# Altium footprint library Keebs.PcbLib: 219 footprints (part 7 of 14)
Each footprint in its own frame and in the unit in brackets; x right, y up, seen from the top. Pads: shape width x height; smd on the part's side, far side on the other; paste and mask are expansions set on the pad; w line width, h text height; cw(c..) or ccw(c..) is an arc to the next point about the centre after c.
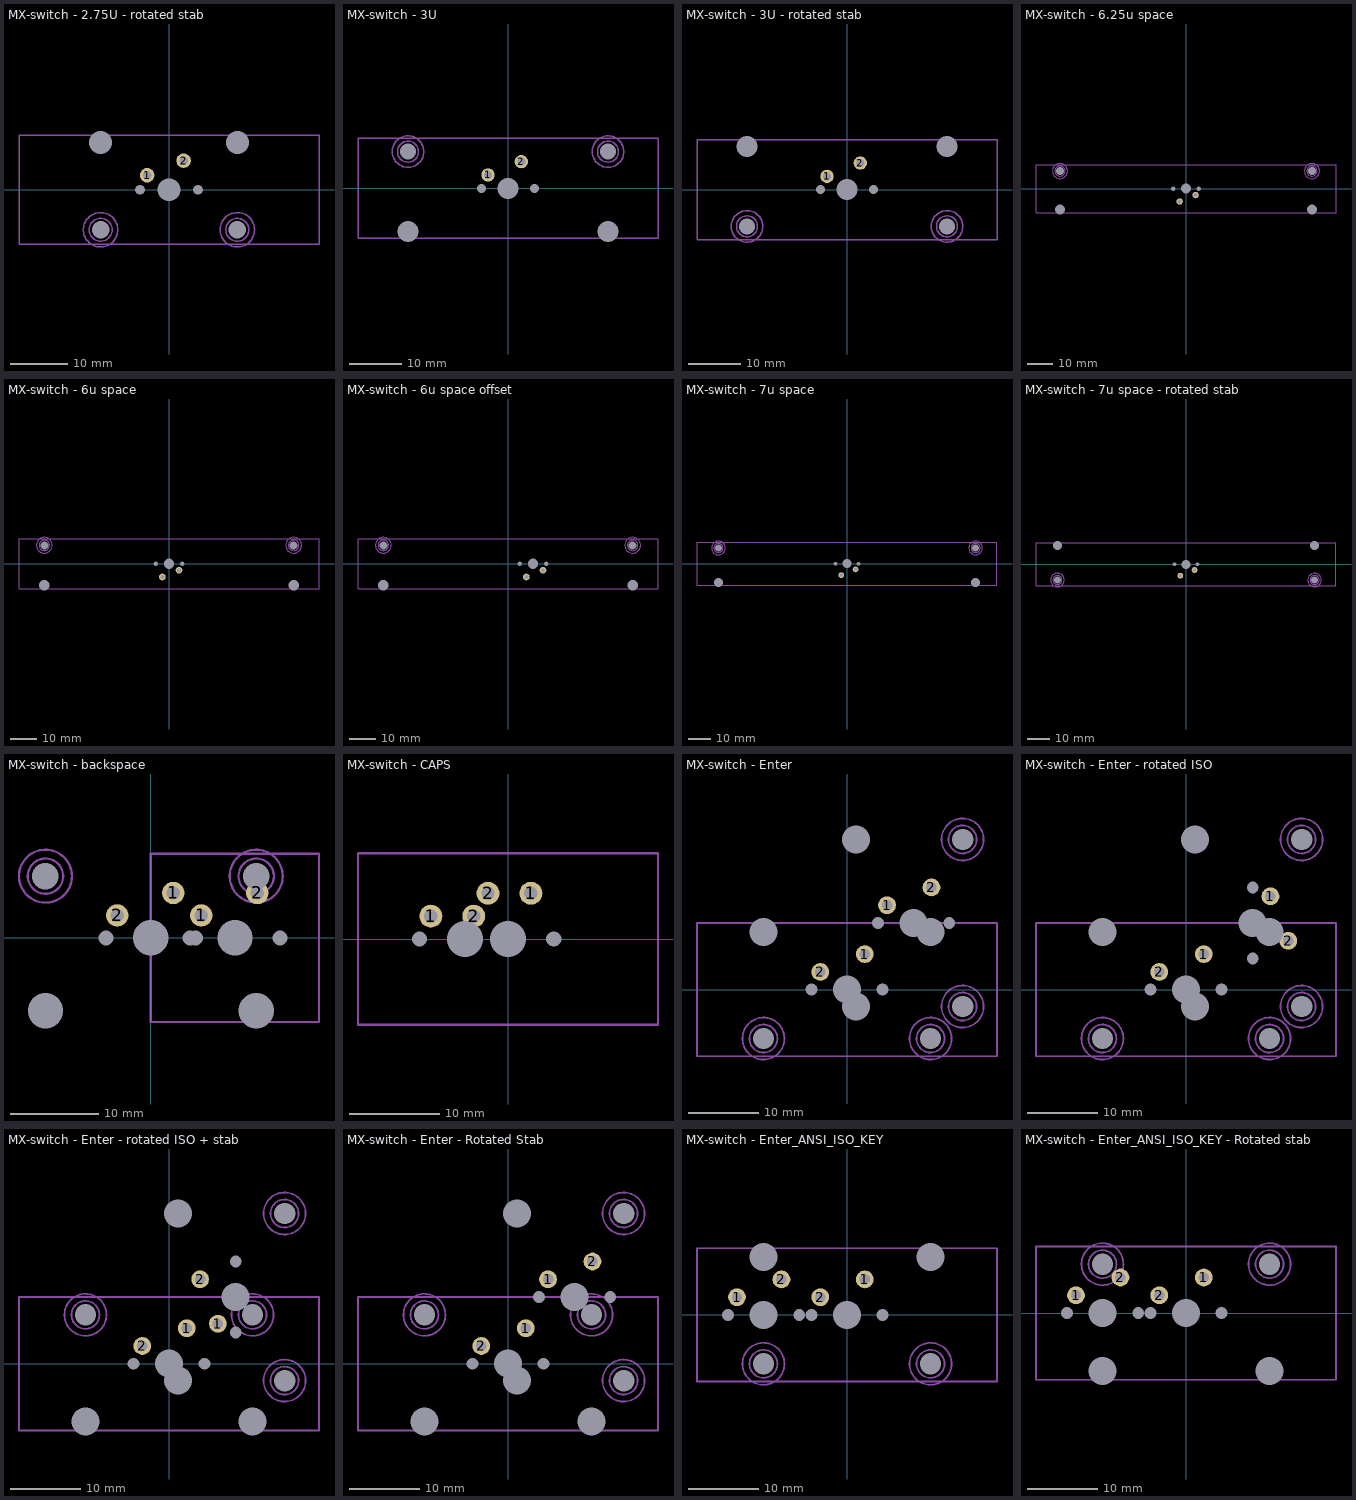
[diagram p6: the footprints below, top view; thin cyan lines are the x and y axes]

## MX-switch - 2.75U - rotated stab [mm]
pads (10):
  round 2.54 hole 1.5 mask-0.5: 1(-3.81,2.54) 2(2.54,5.08)
  round 1.524 hole 3.048 unplated: ""(-11.938,-6.985) ""(11.938,-6.985)
  round 1.524 hole 4 unplated: ""(-11.938,8.255) ""(11.938,8.255)
  round 1 hole 1.7 unplated: ""(-5.08,0) ""(5.08,0)
  round 1 on Mech13: ""(0,0)
  round 1 hole 4 unplated: ""(0,0)
Mechanical 13:
  lines w0.254: -26.194,-9.525 -26.194,9.525 26.194,9.525 26.194,-9.525 -26.194,-9.525
  text ".Designator" at -3.825,-3.375 h0.7
Mechanical 15:
  circle w0.254: c-11.938,-6.985 r2
  circle w0.254: c-11.938,-6.985 r3
  circle w0.254: c11.938,-6.985 r2
  circle w0.254: c11.938,-6.985 r3

## MX-switch - 3U [mm]
pads (10):
  round 2.54 hole 1.5 mask-0.5: 1(-3.81,2.54) 2(2.54,5.08)
  round 1.524 hole 4 unplated: ""(-19.05,-8.255) ""(19.05,-8.255)
  round 1.524 hole 3.048 unplated: ""(-19.05,6.985) ""(19.05,6.985)
  round 1 hole 1.7 unplated: ""(-5.08,0) ""(5.08,0)
  round 1 on Mech13: ""(0,0)
  round 1 hole 4 unplated: ""(0,0)
Mechanical 13:
  lines w0.254: -28.575,-9.525 28.575,-9.525 28.575,9.525 -28.575,9.525 -28.575,-9.525
  text ".Designator" at -3.825,-3.375 h0.7
Mechanical 15:
  circle w0.254: c-19.05,6.985 r3
  circle w0.254: c-19.05,6.985 r2
  circle w0.254: c19.05,6.985 r3
  circle w0.254: c19.05,6.985 r2

## MX-switch - 3U - rotated stab [mm]
pads (10):
  round 2.54 hole 1.5 mask-0.5: 1(-3.81,2.54) 2(2.54,5.08)
  round 1.524 hole 3.048 unplated: ""(-19.05,-6.985) ""(19.05,-6.985)
  round 1.524 hole 4 unplated: ""(-19.05,8.255) ""(19.05,8.255)
  round 1 hole 1.7 unplated: ""(-5.08,0) ""(5.08,0)
  round 1 on Mech13: ""(0,0)
  round 1 hole 4 unplated: ""(0,0)
Mechanical 13:
  lines w0.254: -28.575,-9.525 -28.575,9.525 28.575,9.525 28.575,-9.525 -28.575,-9.525
  text ".Designator" at -3.825,-3.375 h0.7
Mechanical 15:
  circle w0.254: c-19.05,-6.985 r2
  circle w0.254: c-19.05,-6.985 r3
  circle w0.254: c19.05,-6.985 r2
  circle w0.254: c19.05,-6.985 r3

## MX-switch - 6.25u space [mm]
pads (10):
  round 2.54 hole 1.5 mask-0.5: 1(3.81,-2.54) 2(-2.54,-5.08)
  round 1.524 hole 4 unplated: ""(-50,-8.255) ""(50,-8.255)
  round 1.524 hole 3.048 unplated: ""(-50,6.985) ""(50,6.985)
  round 1 hole 1.7 unplated: ""(-5.08,0) ""(5.08,0)
  round 1 hole 4 unplated: ""(0,0)
  round 1 on Mech13: ""(0,0)
Mechanical 13:
  lines w0.254: -59.531,-9.525 59.531,-9.525 59.531,9.525 -59.531,9.525 -59.531,-9.525
  text ".Designator" at -3.575,-3.7 h0.7
Mechanical 15:
  circle w0.254: c-50,6.985 r2
  circle w0.254: c-50,6.985 r3
  circle w0.254: c50,6.985 r2
  circle w0.254: c50,6.985 r3

## MX-switch - 6u space [mm]
pads (10):
  round 2.54 hole 1.499 mask-0.5: 1(3.81,-2.54) 2(-2.54,-5.08)
  round 1.524 hole 4 unplated: ""(-47.5,-8.255) ""(47.5,-8.255)
  round 1.524 hole 3.048 unplated: ""(-47.5,6.985) ""(47.5,6.985)
  round 1 hole 1.7 unplated: ""(-5.08,0) ""(5.08,0)
  round 1 hole 4 unplated: ""(0,0)
  round 1 on Mech13: ""(0,0)
Mechanical 13:
  lines w0.254: -57.15,-9.525 57.15,-9.525 57.15,9.525 -57.15,9.525 -57.15,-9.525
  text ".Designator" at -3.575,-3.7 h0.7
Mechanical 15:
  circle w0.254: c47.5,6.985 r3
  circle w0.254: c47.5,6.985 r2
  circle w0.254: c-47.5,6.985 r3
  circle w0.254: c-47.5,6.985 r2

## MX-switch - 6u space offset [mm]
pads (10):
  round 2.54 hole 1.5 mask-0.5: 1(13.335,-2.54) 2(6.985,-5.08)
  round 1.524 hole 4 unplated: ""(-47.5,-8.255) ""(47.5,-8.255)
  round 1.524 hole 3.048 unplated: ""(-47.5,6.985) ""(47.5,6.985)
  round 1 hole 1.7 unplated: ""(4.445,0) ""(14.605,0)
  round 1 hole 4 unplated: ""(9.525,0)
  round 1 on Mech13: ""(9.525,0)
Mechanical 13:
  lines w0.254: -57.15,-9.525 -57.15,9.525 57.15,9.525 57.15,-9.525 -57.15,-9.525
  text ".Designator" at -3.575,-3.7 h0.7
Mechanical 15:
  circle w0.254: c-47.5,6.985 r2
  circle w0.254: c-47.5,6.985 r3
  circle w0.254: c47.5,6.985 r2
  circle w0.254: c47.5,6.985 r3

## MX-switch - 7u space [mm]
pads (10):
  round 2.54 hole 1.5 mask-0.5: 1(3.81,-2.54) 2(-2.54,-5.08)
  round 1.524 hole 4 unplated: ""(-57.15,-8.255) ""(57.15,-8.255)
  round 1.524 hole 3.048 unplated: ""(-57.15,6.985) ""(57.15,6.985)
  round 1 hole 1.7 unplated: ""(-5.08,0) ""(5.08,0)
  round 1 hole 4 unplated: ""(0,0)
  round 1 on Mech13: ""(0,0)
Mechanical 13:
  lines w0.254: -66.675,-9.525 -66.675,9.525 66.675,9.525 66.675,-9.525 -66.675,-9.525
  text ".Designator" at -3.575,-3.7 h0.7
Mechanical 15:
  circle w0.254: c57.15,6.985 r3
  circle w0.254: c57.15,6.985 r2
  circle w0.254: c-57.15,6.985 r3
  circle w0.254: c-57.15,6.985 r2

## MX-switch - 7u space - rotated stab [mm]
pads (10):
  round 2.54 hole 1.5 mask-0.5: 1(3.81,-2.54) 2(-2.54,-5.08)
  round 1.524 hole 3.048 unplated: ""(-57.15,-6.985) ""(57.15,-6.985)
  round 1.524 hole 4 unplated: ""(-57.15,8.255) ""(57.15,8.255)
  round 1 hole 1.7 unplated: ""(-5.08,0) ""(5.08,0)
  round 1 hole 4 unplated: ""(0,0)
  round 1 on Mech13: ""(0,0)
Mechanical 13:
  lines w0.254: -66.675,-9.525 66.675,-9.525 66.675,9.525 -66.675,9.525 -66.675,-9.525
  text ".Designator" at -3.575,-3.7 h0.7
Mechanical 15:
  circle w0.254: c-57.15,-6.985 r2
  circle w0.254: c-57.15,-6.985 r3
  circle w0.254: c57.15,-6.985 r2
  circle w0.254: c57.15,-6.985 r3

## MX-switch - backspace [mm]
pads (16):
  round 2.54 hole 1.5 mask-0.5: 1(2.54,5.08) 1(5.715,2.54) 2(-3.81,2.54) 2(12.065,5.08)
  round 1.524 hole 4 unplated: ""(-11.938,-8.255) ""(11.938,-8.255)
  round 1.524 hole 3 unplated: ""(-11.938,6.985) ""(11.938,6.985)
  round 1 hole 1.7 unplated: ""(-5.08,0) ""(4.445,0) ""(5.08,0) ""(14.605,0)
  round 1 hole 4 unplated: ""(0,0) ""(9.525,0)
  round 1 on Mech13: ""(0,0) ""(9.525,0)
Mechanical 13:
  lines w0.254: 0,-9.525 0,9.525 19.05,9.525 19.05,-9.525 0,-9.525
  text ".Designator" at 6.65,3.75 h0.7
Mechanical 15:
  circle w0.254: c-11.938,6.985 r2
  circle w0.254: c-11.938,6.985 r3
  circle w0.254: c11.938,6.985 r2
  circle w0.254: c11.938,6.985 r3

## MX-switch - CAPS [mm]
pads (10):
  round 2.54 hole 1.5 mask-0.5: 1(-8.572,2.54) 1(2.54,5.08) 2(-3.81,2.54) 2(-2.222,5.08)
  round 1 hole 1.7 unplated: ""(-9.842,0) ""(5.08,0)
  round 1 on Mech13: ""(-4.763,0) ""(0,0)
  round 1 hole 4 unplated: ""(-4.763,0) ""(0,0)
Mechanical 13:
  lines w0.254: -16.669,-9.525 16.669,-9.525 ; -16.669,-9.525 16.669,-9.525 ; -16.669,-9.525 -16.669,9.525 16.669,9.525 16.669,-9.525
  text ".Designator" at -7.85,-7.5 h0.7

## MX-switch - Enter [mm]
pads (20):
  round 2.54 hole 1.5 mask-0.5: 1(2.54,5.08) 1(5.72,12.07) 2(-3.81,2.54) 2(12.07,14.61)
  round 1.524 hole 3.048 unplated: ""(-11.938,-6.985) ""(11.938,-6.985) ""(16.515,-2.408) ""(16.515,21.468)
  round 1.524 hole 4 unplated: ""(-11.938,8.255) ""(1.275,-2.408) ""(1.275,21.468) ""(11.938,8.255)
  round 1 hole 1.7 unplated: ""(-5.08,0) ""(4.45,9.53) ""(5.08,0) ""(14.61,9.53)
  round 1 hole 4 unplated: ""(0,0) ""(9.53,9.53)
  round 1 on Mech13: ""(0,0) ""(9.53,9.53)
Mechanical 13:
  lines w0.254: -21.431,-9.525 21.431,-9.525 21.431,9.525 -21.431,9.525 -21.431,-9.525
  text ".Designator" at 7.85,1.8 h0.7
Mechanical 15:
  circle w0.254: c-11.938,-6.985 r2
  circle w0.254: c-11.938,-6.985 r3
  circle w0.254: c11.938,-6.985 r2
  circle w0.254: c11.938,-6.985 r3
  circle w0.254: c16.515,-2.408 r2
  circle w0.254: c16.515,-2.408 r3
  circle w0.254: c16.515,21.468 r2
  circle w0.254: c16.515,21.468 r3

## MX-switch - Enter - rotated ISO [mm]
pads (20):
  round 2.54 hole 1.5 mask-0.5: 1(2.54,5.08) 1(12.07,13.34) 2(-3.81,2.54) 2(14.61,6.99)
  round 1.524 hole 3.048 unplated: ""(-11.938,-6.985) ""(11.938,-6.985) ""(16.515,-2.408) ""(16.515,21.468)
  round 1.524 hole 4 unplated: ""(-11.938,8.255) ""(1.275,-2.408) ""(1.275,21.468) ""(11.938,8.255)
  round 1 hole 1.7 unplated: ""(-5.08,0) ""(5.08,0) ""(9.53,4.45) ""(9.53,14.61)
  round 1 hole 4 unplated: ""(0,0) ""(9.53,9.53)
  round 1 on Mech13: ""(0,0) ""(9.53,9.53)
Mechanical 13:
  lines w0.254: -21.431,-9.525 21.431,-9.525 21.431,9.525 -21.431,9.525 -21.431,-9.525
  text ".Designator" at 7.85,1.8 h0.7
Mechanical 15:
  circle w0.254: c-11.938,-6.985 r2
  circle w0.254: c-11.938,-6.985 r3
  circle w0.254: c11.938,-6.985 r2
  circle w0.254: c11.938,-6.985 r3
  circle w0.254: c16.515,-2.408 r2
  circle w0.254: c16.515,-2.408 r3
  circle w0.254: c16.515,21.468 r2
  circle w0.254: c16.515,21.468 r3

## MX-switch - Enter - rotated ISO + stab [mm]
pads (20):
  round 2.54 hole 1.5 mask-0.5: 1(2.54,5.08) 1(6.99,5.72) 2(-3.81,2.54) 2(4.45,12.07)
  round 1.524 hole 4 unplated: ""(-11.938,-8.255) ""(1.275,-2.408) ""(1.275,21.468) ""(11.938,-8.255)
  round 1.524 hole 3.048 unplated: ""(-11.938,6.985) ""(11.938,6.985) ""(16.515,-2.408) ""(16.515,21.468)
  round 1 hole 1.7 unplated: ""(-5.08,0) ""(5.08,0) ""(9.53,4.45) ""(9.53,14.61)
  round 1 hole 4 unplated: ""(0,0) ""(9.53,9.53)
  round 1 on Mech13: ""(0,0) ""(9.53,9.53)
Mechanical 13:
  lines w0.254: -21.431,-9.525 21.431,-9.525 21.431,9.525 -21.431,9.525 -21.431,-9.525
  text ".Designator" at 7.85,1.8 h0.7
Mechanical 15:
  circle w0.254: c11.938,6.985 r2
  circle w0.254: c11.938,6.985 r3
  circle w0.254: c-11.938,6.985 r2
  circle w0.254: c-11.938,6.985 r3
  circle w0.254: c16.515,-2.408 r2
  circle w0.254: c16.515,-2.408 r3
  circle w0.254: c16.515,21.468 r2
  circle w0.254: c16.515,21.468 r3

## MX-switch - Enter - Rotated Stab [mm]
pads (20):
  round 2.54 hole 1.5 mask-0.5: 1(2.54,5.08) 1(5.72,12.07) 2(-3.81,2.54) 2(12.07,14.61)
  round 1.524 hole 4 unplated: ""(-11.938,-8.255) ""(1.275,-2.408) ""(1.275,21.468) ""(11.938,-8.255)
  round 1.524 hole 3.048 unplated: ""(-11.938,6.985) ""(11.938,6.985) ""(16.515,-2.408) ""(16.515,21.468)
  round 1 hole 1.7 unplated: ""(-5.08,0) ""(4.45,9.53) ""(5.08,0) ""(14.61,9.53)
  round 1 hole 4 unplated: ""(0,0) ""(9.53,9.53)
  round 1 on Mech13: ""(0,0) ""(9.53,9.53)
Mechanical 13:
  lines w0.254: -21.431,-9.525 -21.431,9.525 21.431,9.525 21.431,-9.525 -21.431,-9.525
  text ".Designator" at 7.85,1.8 h0.7
Mechanical 15:
  circle w0.254: c11.938,6.985 r3
  circle w0.254: c11.938,6.985 r2
  circle w0.254: c16.515,21.468 r3
  circle w0.254: c16.515,21.468 r2
  circle w0.254: c16.515,-2.408 r3
  circle w0.254: c16.515,-2.408 r2
  circle w0.254: c-11.938,6.985 r3
  circle w0.254: c-11.938,6.985 r2

## MX-switch - Enter_ANSI_ISO_KEY [mm]
pads (18):
  round 2.54 hole 1.5 mask-0.5: 1(-15.716,2.54) 1(2.54,5.08) 2(-9.366,5.08) 2(-3.81,2.54)
  round 1 hole 1.7 unplated: ""(-16.986,0) ""(-6.826,0) ""(-5.08,0) ""(5.08,0)
  round 1.524 hole 3.048 unplated: ""(-11.938,-6.985) ""(11.938,-6.985)
  round 1.524 hole 4 unplated: ""(-11.938,8.255) ""(11.938,8.255)
  round 1 hole 4 unplated: ""(-11.906,0) ""(0,0)
  round 1 on Mech13: ""(-11.906,0) ""(-11.906,0) ""(0,0) ""(0,0)
Mechanical 13:
  lines w0.254: -21.431,-9.525 -21.431,9.525 21.431,9.525 21.431,-9.525 -21.431,-9.525
  text ".Designator" at 7.85,1.8 h0.7
Mechanical 15:
  circle w0.254: c-11.938,-6.985 r2
  circle w0.254: c-11.938,-6.985 r3
  circle w0.254: c11.938,-6.985 r2
  circle w0.254: c11.938,-6.985 r3

## MX-switch - Enter_ANSI_ISO_KEY - Rotated stab [mm]
pads (18):
  round 2.54 hole 1.5 mask-0.5: 1(-15.716,2.54) 1(2.54,5.08) 2(-9.366,5.08) 2(-3.81,2.54)
  round 1 hole 1.7 unplated: ""(-16.986,0) ""(-6.826,0) ""(-5.08,0) ""(5.08,0)
  round 1.524 hole 4 unplated: ""(-11.938,-8.255) ""(11.938,-8.255)
  round 1.524 hole 3.048 unplated: ""(-11.938,6.985) ""(11.938,6.985)
  round 1 hole 4 unplated: ""(-11.906,0) ""(0,0)
  round 1 on Mech13: ""(-11.906,0) ""(-11.906,0) ""(0,0) ""(0,0)
Mechanical 13:
  lines w0.254: -21.431,-9.525 -21.431,9.525 21.431,9.525 21.431,-9.525 -21.431,-9.525
  text ".Designator" at 7.85,1.8 h0.7
Mechanical 15:
  circle w0.254: c11.938,6.985 r3
  circle w0.254: c11.938,6.985 r2
  circle w0.254: c-11.938,6.985 r3
  circle w0.254: c-11.938,6.985 r2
